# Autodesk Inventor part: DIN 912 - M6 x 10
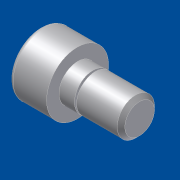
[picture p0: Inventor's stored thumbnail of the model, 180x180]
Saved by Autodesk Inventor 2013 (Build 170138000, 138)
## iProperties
Created: 2002-02
Part Number: DIN 912 - M6 x 10
Material: Standard
Catalog Web Link: file:///C:/Programme/Autodesk/Inventor 5/Content/Din/index.htm?doNavigateId=32E941FC-C430-11D4-A9F1-0080AD303E0A|0557D50BB16611D4BA6900C04F798F98|true
Description: Zylinderschraube
Document SubType Name: Standard Catalog Part
Standard: DIN 912 - M6 x 10
Designer: dl
Density: 1 g/cm^3
Control State: 0
Master: False
Checked Out: False
Shininess: 20.0
Length Units: 11269
Angle Units: 11279
Time Units: 11290
Mass Units: 11283
Length Display Precision: 3
Angle Display Precision: 2
CLASSIFICATION: 31161501 un/spsc
MANUFACTURER: DIN Normsystem
Density: 0.0
Volumn: 0.0
Area: 0.0
PropertySet Name: Model Information
Author: dl
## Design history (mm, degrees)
feature "Basis1"
body "Solid1"
